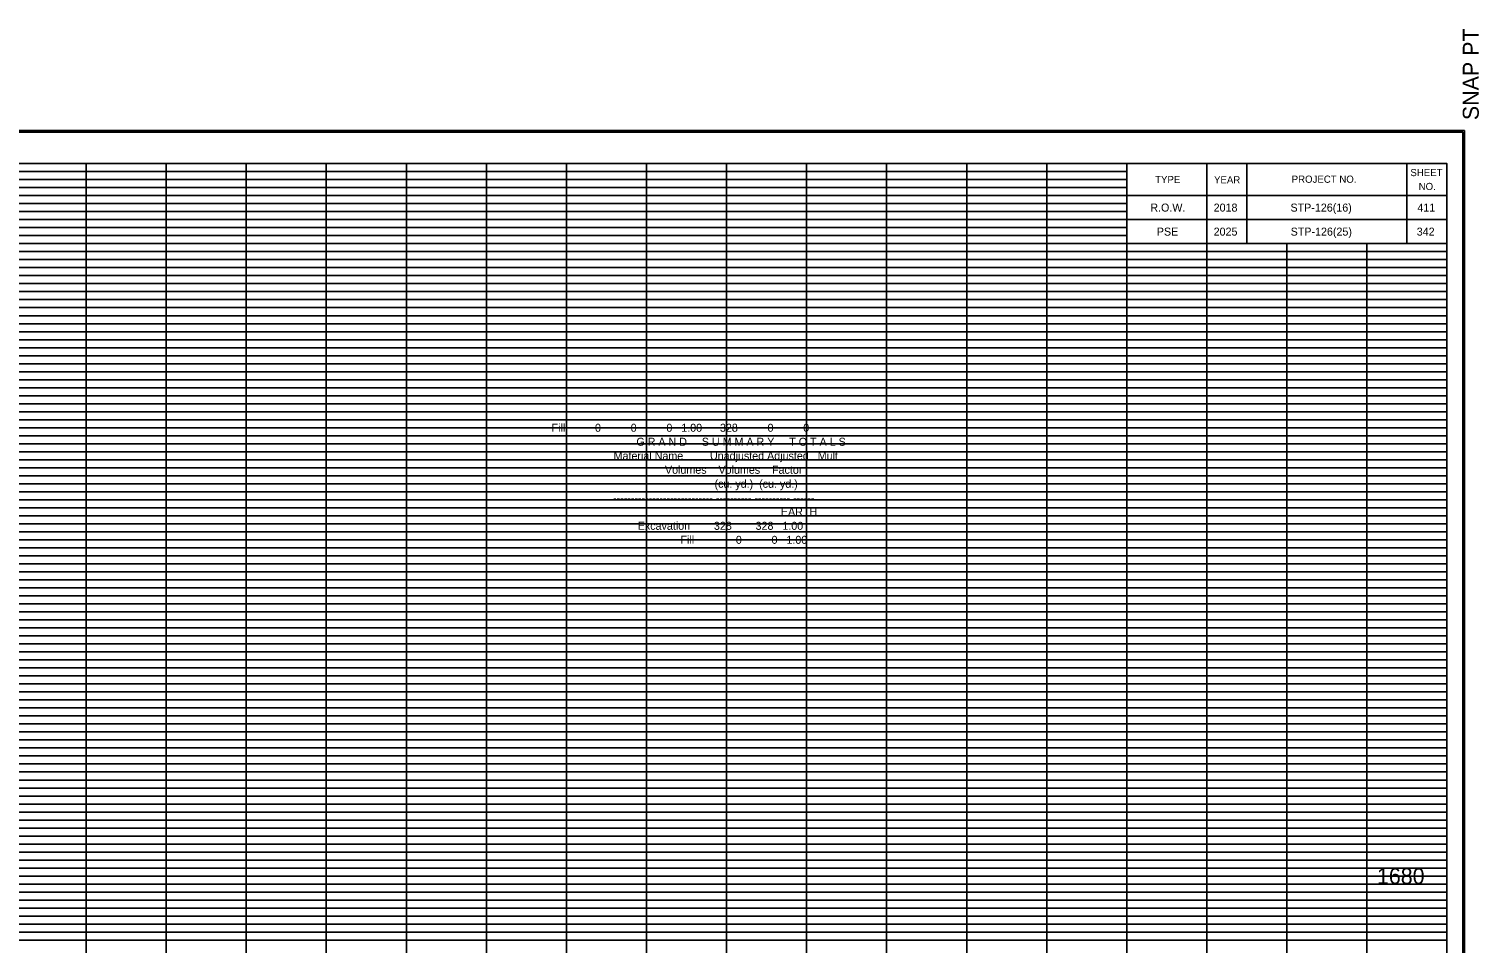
# Model space of a CAD drawing. Extents: x 980 to 1324, y 978 to 1767.
# Drawn here: x 1142.9 to 1324, y 1382.5 to 1496.8 of the extents above; entities that cross this region are included whole.
import ezdxf

# ---------------------------------------------------------------- set-up
doc = ezdxf.new("R2010")
doc.units = 0
for name, color, linetype in [('DESIGN - SCRATCH - User 1', 7, 'Continuous'), ('DESIGN - SHEET - Corner Text', 7, 'Continuous'), ('DESIGN - SHEET - Light Grid', 7, 'Continuous'), ('DESIGN - SHEET - Linework', 7, 'Continuous'), ('DESIGN - SHEET - Plot Shape', 7, 'Continuous'), ('DESIGN - TYPICAL - Finished Grade and Subgrade', 7, 'Continuous'), ('DESIGN - TYPICAL - Text', 7, 'Continuous')]:
    doc.layers.add(name, color=color, linetype=linetype)

# ---------------------------------------------------------------- blocks, each defined once
blk = doc.blocks.new('XSTSHT')
at = {"layer": 'DESIGN - SCRATCH - User 1'}
for p, q in [((28.5, 20.45), (28.5, 20.45)), ((29.24, 20.45), (29.24, 20.45)), ((30.49, 20.45), (30.49, 20.45)), ((31.74, 20.45), (31.74, 20.45)), ((28.5, 20.15), (28.5, 20.15)), ((29.24, 20.15), (29.24, 20.15)), ((30.49, 20.15), (30.49, 20.15)), ((31.74, 20.15), (31.74, 20.15))]:
    blk.add_line(p, q, dxfattribs=at)
at = {"layer": 'DESIGN - SHEET - Light Grid'}
for p, q in [((8, 20.9), (16, 20.9)), ((16, 20.9), (24, 20.9)), ((24, 20.9), (28, 20.9)), ((8, 20.8), (16, 20.8)), ((8, 20.7), (16, 20.7)), ((16, 20.8), (24, 20.8)), ((16, 20.7), (24, 20.7)), ((24, 20.8), (28, 20.8)), ((24, 20.7), (28, 20.7)), ((8, 20.6), (16, 20.6)), ((8, 20.5), (16, 20.5)), ((16, 20.6), (24, 20.6)), ((16, 20.5), (24, 20.5)), ((24, 20.6), (28, 20.6)), ((24, 20.5), (28, 20.5)), ((8, 20.4), (16, 20.4)), ((8, 20.3), (16, 20.3)), ((16, 20.4), (24, 20.4)), ((16, 20.3), (24, 20.3)), ((24, 20.4), (28, 20.4)), ((24, 20.3), (28, 20.3)), ((8, 20.2), (16, 20.2)), ((16, 20.2), (24, 20.2)), ((24, 20.2), (28, 20.2)), ((8, 20.1), (16, 20.1)), ((16, 20.1), (24, 20.1)), ((24, 20.1), (28, 20.1)), ((8, 19.9), (16, 19.9)), ((8, 19.8), (16, 19.8)), ((16, 19.9), (24, 19.9)), ((16, 19.8), (24, 19.8)), ((24, 19.9), (32, 19.9)), ((24, 19.8), (32, 19.8)), ((8, 19.7), (16, 19.7)), ((8, 19.6), (16, 19.6)), ((16, 19.7), (24, 19.7)), ((16, 19.6), (24, 19.6)), ((24, 19.7), (32, 19.7)), ((24, 19.6), (32, 19.6)), ((8, 19.5), (16, 19.5)), ((8, 19.4), (16, 19.4)), ((16, 19.5), (24, 19.5)), ((16, 19.4), (24, 19.4)), ((24, 19.5), (32, 19.5)), ((24, 19.4), (32, 19.4)), ((8, 19.3), (16, 19.3)), ((16, 19.3), (24, 19.3)), ((24, 19.3), (32, 19.3)), ((8, 19.2), (16, 19.2)), ((8, 19.1), (16, 19.1)), ((16, 19.2), (24, 19.2)), ((16, 19.1), (24, 19.1)), ((24, 19.2), (32, 19.2)), ((24, 19.1), (32, 19.1)), ((8, 18.9), (16, 18.9)), ((16, 18.9), (24, 18.9)), ((24, 18.9), (32, 18.9)), ((8, 18.8), (16, 18.8)), ((8, 18.7), (16, 18.7)), ((16, 18.8), (24, 18.8)), ((16, 18.7), (24, 18.7)), ((24, 18.8), (32, 18.8)), ((24, 18.7), (32, 18.7)), ((8, 18.6), (16, 18.6)), ((8, 18.5), (16, 18.5)), ((16, 18.6), (24, 18.6)), ((16, 18.5), (24, 18.5)), ((24, 18.6), (32, 18.6)), ((24, 18.5), (32, 18.5)), ((8, 18.4), (16, 18.4)), ((8, 18.3), (16, 18.3)), ((16, 18.4), (24, 18.4)), ((16, 18.3), (24, 18.3)), ((24, 18.4), (32, 18.4)), ((24, 18.3), (32, 18.3)), ((8, 18.2), (16, 18.2)), ((16, 18.2), (24, 18.2)), ((24, 18.2), (32, 18.2)), ((8, 18.1), (16, 18.1)), ((16, 18.1), (24, 18.1)), ((24, 18.1), (32, 18.1)), ((8, 17.9), (16, 17.9)), ((8, 17.8), (16, 17.8)), ((16, 17.9), (24, 17.9)), ((16, 17.8), (24, 17.8)), ((24, 17.9), (32, 17.9)), ((24, 17.8), (32, 17.8)), ((8, 17.7), (16, 17.7)), ((8, 17.6), (16, 17.6)), ((16, 17.7), (24, 17.7)), ((16, 17.6), (24, 17.6)), ((24, 17.7), (32, 17.7)), ((24, 17.6), (32, 17.6)), ((8, 17.5), (16, 17.5)), ((8, 17.4), (16, 17.4)), ((16, 17.5), (24, 17.5)), ((16, 17.4), (24, 17.4)), ((24, 17.5), (32, 17.5)), ((24, 17.4), (32, 17.4)), ((8, 17.3), (16, 17.3)), ((16, 17.3), (24, 17.3)), ((24, 17.3), (32, 17.3)), ((8, 17.2), (16, 17.2)), ((8, 17.1), (16, 17.1)), ((16, 17.2), (24, 17.2)), ((16, 17.1), (24, 17.1)), ((24, 17.2), (32, 17.2)), ((24, 17.1), (32, 17.1)), ((8, 16.9), (16, 16.9)), ((16, 16.9), (24, 16.9)), ((24, 16.9), (32, 16.9)), ((8, 16.8), (16, 16.8)), ((8, 16.7), (16, 16.7)), ((16, 16.8), (24, 16.8)), ((16, 16.7), (24, 16.7)), ((24, 16.8), (32, 16.8)), ((24, 16.7), (32, 16.7)), ((8, 16.6), (16, 16.6)), ((8, 16.5), (16, 16.5)), ((16, 16.6), (24, 16.6)), ((16, 16.5), (24, 16.5)), ((24, 16.6), (32, 16.6)), ((24, 16.5), (32, 16.5)), ((8, 16.4), (16, 16.4)), ((16, 16.4), (24, 16.4)), ((24, 16.4), (32, 16.4)), ((8, 16.3), (16, 16.3)), ((8, 16.2), (16, 16.2)), ((16, 16.3), (24, 16.3)), ((16, 16.2), (24, 16.2)), ((24, 16.3), (32, 16.3)), ((24, 16.2), (32, 16.2)), ((8, 16.1), (16, 16.1)), ((16, 16.1), (24, 16.1)), ((24, 16.1), (32, 16.1)), ((8, 15.9), (16, 15.9)), ((8, 15.8), (16, 15.8)), ((16, 15.9), (24, 15.9)), ((16, 15.8), (24, 15.8)), ((24, 15.9), (32, 15.9)), ((24, 15.8), (32, 15.8)), ((8, 15.7), (16, 15.7)), ((8, 15.6), (16, 15.6)), ((16, 15.7), (24, 15.7)), ((16, 15.6), (24, 15.6)), ((24, 15.7), (32, 15.7)), ((24, 15.6), (32, 15.6)), ((8, 15.5), (16, 15.5)), ((8, 15.4), (16, 15.4)), ((16, 15.5), (24, 15.5)), ((16, 15.4), (24, 15.4)), ((24, 15.5), (32, 15.5)), ((24, 15.4), (32, 15.4)), ((8, 15.3), (16, 15.3)), ((16, 15.3), (24, 15.3)), ((24, 15.3), (32, 15.3)), ((8, 15.2), (16, 15.2)), ((8, 15.1), (16, 15.1)), ((16, 15.2), (24, 15.2)), ((16, 15.1), (24, 15.1)), ((24, 15.2), (32, 15.2)), ((24, 15.1), (32, 15.1)), ((8, 14.9), (16, 14.9)), ((16, 14.9), (24, 14.9)), ((24, 14.9), (32, 14.9)), ((8, 14.8), (16, 14.8)), ((8, 14.7), (16, 14.7)), ((16, 14.8), (24, 14.8)), ((16, 14.7), (24, 14.7)), ((24, 14.8), (32, 14.8)), ((24, 14.7), (32, 14.7)), ((8, 14.6), (16, 14.6)), ((8, 14.5), (16, 14.5)), ((16, 14.6), (24, 14.6)), ((16, 14.5), (24, 14.5)), ((24, 14.6), (32, 14.6)), ((24, 14.5), (32, 14.5)), ((8, 14.4), (16, 14.4)), ((16, 14.4), (24, 14.4)), ((24, 14.4), (32, 14.4)), ((8, 14.3), (16, 14.3)), ((8, 14.2), (16, 14.2)), ((16, 14.3), (24, 14.3)), ((16, 14.2), (24, 14.2)), ((24, 14.3), (32, 14.3)), ((24, 14.2), (32, 14.2)), ((8, 14.1), (16, 14.1)), ((16, 14.1), (24, 14.1)), ((24, 14.1), (32, 14.1)), ((8, 13.9), (16, 13.9)), ((8, 13.8), (16, 13.8)), ((16, 13.9), (24, 13.9)), ((16, 13.8), (24, 13.8)), ((24, 13.9), (32, 13.9)), ((24, 13.8), (32, 13.8)), ((8, 13.7), (16, 13.7)), ((8, 13.6), (16, 13.6)), ((16, 13.7), (24, 13.7)), ((16, 13.6), (24, 13.6)), ((24, 13.7), (32, 13.7)), ((24, 13.6), (32, 13.6)), ((8, 13.5), (16, 13.5)), ((16, 13.5), (24, 13.5)), ((24, 13.5), (32, 13.5)), ((8, 13.4), (16, 13.4)), ((8, 13.3), (16, 13.3)), ((16, 13.4), (24, 13.4)), ((16, 13.3), (24, 13.3)), ((24, 13.4), (32, 13.4)), ((24, 13.3), (32, 13.3)), ((8, 13.2), (16, 13.2)), ((8, 13.1), (16, 13.1)), ((16, 13.2), (24, 13.2)), ((16, 13.1), (24, 13.1)), ((24, 13.2), (32, 13.2)), ((24, 13.1), (32, 13.1)), ((8, 12.9), (16, 12.9)), ((16, 12.9), (24, 12.9)), ((24, 12.9), (32, 12.9)), ((8, 12.8), (16, 12.8)), ((8, 12.7), (16, 12.7)), ((16, 12.8), (24, 12.8)), ((16, 12.7), (24, 12.7)), ((24, 12.8), (32, 12.8)), ((24, 12.7), (32, 12.7)), ((8, 12.6), (16, 12.6)), ((8, 12.5), (16, 12.5)), ((16, 12.6), (24, 12.6)), ((16, 12.5), (24, 12.5)), ((24, 12.6), (32, 12.6)), ((24, 12.5), (32, 12.5)), ((8, 12.4), (16, 12.4)), ((16, 12.4), (24, 12.4)), ((24, 12.4), (32, 12.4)), ((8, 12.3), (16, 12.3)), ((8, 12.2), (16, 12.2)), ((16, 12.3), (24, 12.3)), ((16, 12.2), (24, 12.2)), ((24, 12.3), (32, 12.3)), ((24, 12.2), (32, 12.2)), ((8, 12.1), (16, 12.1)), ((16, 12.1), (24, 12.1)), ((24, 12.1), (32, 12.1)), ((8, 11.9), (16, 11.9)), ((8, 11.8), (16, 11.8)), ((16, 11.9), (24, 11.9)), ((16, 11.8), (24, 11.8)), ((24, 11.9), (32, 11.9)), ((24, 11.8), (32, 11.8)), ((8, 11.7), (16, 11.7)), ((8, 11.6), (16, 11.6)), ((16, 11.7), (24, 11.7)), ((16, 11.6), (24, 11.6)), ((24, 11.7), (32, 11.7)), ((24, 11.6), (32, 11.6)), ((8, 11.5), (16, 11.5)), ((16, 11.5), (24, 11.5)), ((24, 11.5), (32, 11.5)), ((8, 11.4), (16, 11.4)), ((8, 11.3), (16, 11.3)), ((16, 11.4), (24, 11.4)), ((16, 11.3), (24, 11.3)), ((24, 11.4), (32, 11.4)), ((24, 11.3), (32, 11.3))]:
    blk.add_line(p, q, dxfattribs=at)
at = {"layer": 'DESIGN - SHEET - Linework'}
for p, q in [((-1.823, 21.414), (32.217, 21.414)), ((32.217, 21.414), (32.217, -0.414)), ((15, 0), (15, 21)), ((16, 0), (16, 21)), ((17, 0), (17, 21)), ((18, 0), (18, 21)), ((19, 0), (19, 21)), ((20, 0), (20, 21)), ((21, 0), (21, 21)), ((22, 0), (22, 21)), ((23, 0), (23, 21)), ((24, 0), (24, 21)), ((25, 0), (25, 21)), ((26, 0), (26, 21)), ((27, 0), (27, 21)), ((0, 20), (28, 20)), ((28, 0), (28, 20)), ((29, 0), (29, 20)), ((30, 0), (30, 20)), ((31, 0), (31, 20)), ((0, 19), (32, 19)), ((0, 18), (32, 18)), ((0, 17), (32, 17)), ((0, 16), (32, 16)), ((0, 15), (32, 15)), ((0, 14), (32, 14)), ((0, 13), (32, 13)), ((0, 12), (32, 12))]:
    blk.add_line(p, q, dxfattribs=at)
for points in [[(0, 21), (0, 0), (32, 0), (32, 21), (0, 21)], [(28, 21), (28, 20), (32, 20), (32, 21), (31.5, 21), (31.5, 20), (29.5, 20), (29.5, 21), (29, 21), (29, 20), (32, 20), (28, 20), (28, 20.3), (32, 20.3), (32, 20.6), (28, 20.6)]]:
    blk.add_lwpolyline(points, dxfattribs=at)
at = {"layer": 'DESIGN - SHEET - Plot Shape'}
for points in [[(-1.803, 21.394), (32.197, 21.394), (32.197, -0.394), (-1.803, -0.394)], [(-0.85, 21), (32, 21), (32, -0.25), (-0.85, -0.25)]]:
    blk.add_lwpolyline(points, close=True, dxfattribs=at)
at = {"layer": 'DESIGN - SHEET - Corner Text'}
blk.add_text('  SNAP PT', height=0.2, rotation=90, dxfattribs=at).set_placement((32.397, 21.394))
for s, p in [('TYPE', (28.354, 20.756)), ('YEAR', (29.09, 20.752)), ('PROJECT NO.', (30.06, 20.76)), ('SHEET', (31.543, 20.843)), ('NO.', (31.646, 20.669))]:
    blk.add_text(s, height=0.09, dxfattribs=at).set_placement(p)

msp = doc.modelspace()

# ---------------------------------------------------------------- linework, layer by layer
at = {"layer": 'DESIGN - SHEET - Plot Shape'}
msp.add_lwpolyline([(991.5, 1480), (1320, 1480), (1320, 1267.5), (991.5, 1267.5)], close=True, dxfattribs=at)

# ---------------------------------------------------------------- block references
at = {"layer": 'DESIGN - TYPICAL - Finished Grade and Subgrade', "xscale": 10, "yscale": 10}
msp.add_blockref('XSTSHT', (1000, 1270), dxfattribs=at)

# ---------------------------------------------------------------- texts
at = {"layer": 'DESIGN - SHEET - Corner Text'}
for s, height, p in [('R.O.W.', 1, (1282.94, 1474)), ('2018', 1, (1290.85, 1474)), ('STP-126(16)', 1, (1300.45, 1474)), ('411', 1, (1316.3, 1474)), ('PSE', 1, (1283.75, 1471)), ('2025', 1, (1290.85, 1471)), ('STP-126(25)', 1, (1300.47, 1471)), ('342', 1, (1316.22, 1471)), ('1680', 2, (1311.25, 1390))]:
    msp.add_text(s, height=height, dxfattribs=at).set_placement(p)
at = {"layer": 'DESIGN - TYPICAL - Text'}
for s, p in [('   Fill          0          0          0   1.00      328          0          0', (1207.03, 1446.5)), ('                  G R A N D     S U M M A R Y     T O T A L S', (1212.05, 1444.75)), ('               Material Name         Unadjusted Adjusted   Mult', (1210.32, 1443)), ('                                     Volumes    Volumes    Factor', (1208.56, 1441.25)), ('                                     (cu. yd.)  (cu. yd.)', (1214.75, 1439.5)), ('        ---------------------------- ---------- ---------- ------', (1212.85, 1437.75)), ('        EARTH', (1233.82, 1436)), ('                          Excavation        328        328   1.00', (1209.25, 1434.25)), ('                            Fill              0          0   1.00', (1213.85, 1432.5))]:
    msp.add_text(s, height=1, dxfattribs=at).set_placement(p)

doc.saveas('drawing.dxf')
